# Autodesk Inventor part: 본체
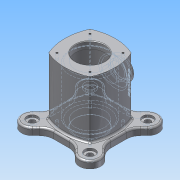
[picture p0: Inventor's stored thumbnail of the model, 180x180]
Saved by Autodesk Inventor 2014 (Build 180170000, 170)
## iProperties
Created: 2016-05
Part Number: 본체
Material: 알루미늄 6061
Document SubType Name: Modeling
Designer: Administrator
Density: 2.71 g/cm^3
Appearance: 알루미늄 - 평지
Mass: 1164.04 g
Surface Area: 856.901 cm^2
Volume: 429.534 cm^3
Author: Administrator
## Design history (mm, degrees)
sketch "스케치1"
  geometry: L1 (-43, 43)-(43, 43); L2 (43, 43)-(43, -43); L3 (43, -43)-(-43, -43); L4 (-43, -43)-(-43, 43); L5 (-43, 43)-(43, -43); L6 (43, 43)-(-43, -43); L7 (0, 0)-(35.355, 35.355); L8 (0, 0)-(-35.355, -35.355); L9 (0, 0)-(-35.355, 35.355); L10 (0, 0)-(35.355, -35.355); A1 r 85.579 centre (0, -42.579) between (35.355, 35.355) and (-35.355, 35.355); A2 r 86 centre (43, -0.091) between (-35.355, 35.355) and (-35.412, -35.412); A3 r 86 centre (-0.091, 43) between (-35.412, -35.412) and (35.355, -35.355); A4 r 85.579 centre (-42.579, 0) between (35.355, -35.355) and (35.355, 35.355)
  constraints: 20 end point, 9 point on circle, 5 point on line, 4 centre point, 4 tangent, 2 midpoint, 2 parallel, 1 horizontal, 1 perpendicular
  dimensions: "d1" = 86 distance of L2.end L3.end; "d2" = 86 distance of L1.end L2.end; "d3" = 50 distance of L7.start L7.end; "d4" = 50 distance of L7.start L8.end; "d5" = 50 distance of L7.start L9.end; "d6" = 50 distance of L7.start L10.end
extrude "돌출1" new body sketch "스케치1" distance "d7" = 110; taper "d8" = 0 deg
node "작업 평면1"
sketch "스케치2"
  geometry: L1 (35.355, 0)-(-35.355, 0) reference; C1 r 20 at (0, 61); 1 further point
  constraints: 1 centre point, 1 vertical alignment
  dimensions: "d10" = 40 diameter of C1; "d11" = 61 distance from line of L1 C1.centre
extrude "돌출2" join sketch "스케치2" stored distance "d12" = 110; taper "d13" = 10 deg
sketch "스케치4"
  geometry: C1 r 25 at (0, 0); 1 further point
  constraints: 1 centre point, 1 coincident
  dimensions: "d14" = 50 diameter of C1
extrude "돌출3" cut sketch "스케치4" stored distance "d15" = 110; taper "d16" = 0 deg
sketch "스케치5"
  geometry: L1 (0, 12)-(0, 98); L2 (-25, 110)-(25, 110) reference; L3 (55, 41)-(43, 38.884) reference; L4 (43, 38.884)-(43, 0) reference; L5 (43, 0)-(25, 0) reference; L6 (25, 0)-(25, 110) reference; L7 (25, 110)-(43, 110) reference; L8 (43, 110)-(43, 83.116) reference; L9 (43, 83.116)-(55, 81) reference; L10 (55, 81)-(55, 41) reference; L11 (-43, 0)-(-43, 110) reference; L12 (-43, 110)-(-25, 110) reference; L13 (-25, 110)-(-25, 0) reference; L14 (-25, 0)-(-43, 0) reference; L15 (0, 98)-(35, 98); L16 (35, 98)-(35, 12); L17 (35, 12)-(0, 12); 3 further points
  constraints: 9 end point, 2 midpoint, 2 perpendicular, 1 horizontal alignment, 1 parallel, 1 vertical alignment
  dimensions: "d20" = 86 distance of L1.start L1.end; "d21" = 35 distance of L15.end L1.end; "d22" = 86 distance of L15.end L16.end
revolve "회전1" sketch "스케치5" stored, may be unused: angle "d23" = 90 deg
hole "구멍1" diameter "d26" = 25; stored, may be unused: countersink angle "d30" = 90 deg, drill point angle "d32" = 118 deg; dims "d24" = 10, "d25" = 10, "d27" = 6, "d28" = 30, "d29" = 8, "d31" = 25
sketch "스케치9"
  geometry: L1 (-23.544, 49)-(23.544, 49); L2 (49, 23.544)-(49, -23.544); L3 (23.544, -49)-(-23.544, -49); L4 (-49, -23.544)-(-49, 23.544); L5 (-62.225, 36.77)-(-49, 23.544); L6 (-36.77, 62.225)-(-23.544, 49); L7 (49, -23.544)-(62.225, -36.77); L8 (23.544, -49)-(36.77, -62.225); L9 (36.77, 62.225)-(23.544, 49); L10 (49, 23.544)-(62.225, 36.77); L11 (-49, -23.544)-(-62.225, -36.77); L12 (-36.77, -62.225)-(-23.544, -49); C1 r 25 at (0, 0) reference; C2 r 25 at (0, 0); A1 r 85.579 centre (0, -42.579) between (35.355, 35.355) and (-35.355, 35.355) reference; A2 r 85.579 centre (42.579, 0) between (-35.355, 35.355) and (-35.355, -35.355) reference; A3 r 86 centre (0.091, 43) between (-35.355, -35.355) and (35.412, -35.412) reference; A4 r 86 centre (-43, -0.091) between (35.412, -35.412) and (35.355, 35.355) reference; A5 r 70 centre (0, 0) between (-35.239, 60.483) and (-60.483, -35.239); A6 r 18 centre (49.497, 49.497) between (62.225, 36.77) and (36.77, 62.225); A7 r 18 centre (-49.497, 49.497) between (-36.77, 62.225) and (-62.225, 36.77); A8 r 18 centre (-49.497, -49.497) between (-62.225, -36.77) and (-36.77, -62.225); A9 r 18 centre (49.497, -49.497) between (36.77, -62.225) and (62.225, -36.77)
  constraints: 24 end point, 10 point on circle, 6 centre point, 2 coincident, 2 parallel, 1 horizontal, 1 perpendicular
  dimensions: "d48" = 140 diameter of A5; "d49" = 36 diameter of A6; "d50" = 36 diameter of A7; "d51" = 36 diameter of A8; "d52" = 36 diameter of A9; "d59" = 98 distance between parallel lines of L2 L4; "d60" = 98 distance between parallel lines of L3 L1; "d61" = 36 distance between parallel lines of L6 L5; "d62" = 36 distance between parallel lines of L12 L11; "d63" = 36 distance between parallel lines of L7 L8; "d64" = 36 distance between parallel lines of L9 L10; "d65" = 50 diameter of C2; "d66" = 49 distance from line of L1 C2.centre; "d67" = 49 distance from line of L2 C1.centre; "d68" = 49.49747 horizontal distance of A6.centre C1.centre; "d69" = 90 deg angle of L11 L5; "d70" = 135 deg angle of L7 L2; "d71" = 90 deg angle of L7 L10; "d72" = 90 deg angle of L12 L8; "d73" = 49.49747 horizontal distance of A9.centre C1.centre; "d74" = 49.49747 horizontal distance of A8.centre C2.centre
extrude "돌출5" join sketch "스케치9" distance "d75" = 12; taper "d76" = 0 deg
fillet "모깎기1" dims "d77" = 25
sketch "스케치12"
  geometry: L1 (-49, -13.189)-(-49, 13.189) reference; L2 (-56.322, 30.866)-(-62.225, 36.77) reference; L3 (-36.77, 62.225)-(-30.866, 56.322) reference; L4 (-13.189, 49)-(13.189, 49) reference; L5 (30.866, 56.322)-(36.77, 62.225) reference; L6 (62.225, 36.77)-(56.322, 30.866) reference; L7 (49, 13.189)-(49, -13.189) reference; L8 (56.322, -30.866)-(62.225, -36.77) reference; L9 (36.77, -62.225)-(30.866, -56.322) reference; L10 (13.189, -49)-(-13.189, -49) reference; L11 (-30.866, -56.322)-(-36.77, -62.225) reference; L12 (-62.225, -36.77)-(-56.322, -30.866) reference; C1 r 25 at (0, 0) reference; A1 r 18 centre (49.497, -49.497) between (36.77, -62.225) and (62.225, -36.77) reference; A2 r 18 centre (49.497, 49.497) between (62.225, 36.77) and (36.77, 62.225) reference; A3 r 18 centre (-49.497, 49.497) between (-36.77, 62.225) and (-62.225, 36.77) reference; A4 r 25 centre (-74, -13.189) between (-56.322, -30.866) and (-49, -13.189) reference; A5 r 25 centre (-74, 13.189) between (-49, 13.189) and (-56.322, 30.866) reference; A6 r 18 centre (-49.497, 49.497) between (-36.77, 62.225) and (-62.225, 36.77) reference; A7 r 25 centre (-13.189, 74) between (-30.866, 56.322) and (-13.189, 49) reference; A8 r 25 centre (13.189, 74) between (13.189, 49) and (30.866, 56.322) reference; A9 r 18 centre (49.497, 49.497) between (62.225, 36.77) and (36.77, 62.225) reference; A10 r 25 centre (74, 13.189) between (56.322, 30.866) and (49, 13.189) reference; A11 r 25 centre (74, -13.189) between (49, -13.189) and (56.322, -30.866) reference; A12 r 18 centre (49.497, -49.497) between (36.77, -62.225) and (62.225, -36.77) reference; A13 r 25 centre (13.189, -74) between (30.866, -56.322) and (13.189, -49) reference; A14 r 25 centre (-13.189, -74) between (-13.189, -49) and (-30.866, -56.322) reference; A15 r 18 centre (-49.497, -49.497) between (-62.225, -36.77) and (-36.77, -62.225) reference
hole "구멍2" sketch "스케치12" at (49.497, 49.497), (-49.497, 49.497), (-49.497, -49.497), (49.497, -49.497) diameter "d78" = 10; stored, may be unused: countersink angle "d82" = 90 deg, drill point angle "d84" = 118 deg; dims "d79" = 6, "d80" = 4, "d81" = 2, "d83" = 8
sketch "스케치13"
  geometry: C1 r 5 at (49.497, -49.497) reference; C2 r 5 at (-49.497, 49.497) reference; C3 r 5 at (49.497, 49.497) reference; C4 r 5 at (-49.497, -49.497) reference; C5 r 9 at (-49.497, 49.497); C6 r 9 at (49.497, 49.497); C7 r 9 at (-49.497, -49.497); C8 r 9 at (49.497, -49.497); A1 r 18 centre (49.497, 49.497) between (62.225, 36.77) and (36.77, 62.225) reference; A2 r 18 centre (-49.497, 49.497) between (-36.77, 62.225) and (-62.225, 36.77) reference; A3 r 18 centre (-49.497, -49.497) between (-62.225, -36.77) and (-36.77, -62.225) reference; A4 r 18 centre (49.497, -49.497) between (36.77, -62.225) and (62.225, -36.77) reference; 1 further point
  constraints: 4 centre point, 4 coincident
  dimensions: "d85" = 18 diameter of C5; "d86" = 18 diameter of C6; "d87" = 18 diameter of C7; "d88" = 18 diameter of C8
extrude "돌출6" cut sketch "스케치13" distance "d89" = 4; taper "d90" = 0 deg
sketch "스케치14" dims "d91" = 80
  geometry: L1 (0, 0)-(28.284, 28.284); L2 (0, 0)-(45, 0); C1 r 25 at (0, 0) reference; 1 further point
  constraints: 4 end point, 2 coincident, 1 horizontal, 3 other
  dimensions: "d93" = 45 deg angle of L2 L1
hole "구멍3" sketch "스케치14" at (28.284, 28.284) diameter "d94" = 3.242; stored, may be unused: countersink angle "d98" = 90 deg, drill point angle "d100" = 118 deg; dims "d95" = 7, "d96" = 4, "d97" = 2, "d99" = 10
fillet "모깎기2" dims "d104" = 3
sketch "스케치15" dims "d105" = 80
  geometry: L1 (-62.225, 36.77)-(-56.322, 30.866) reference; L2 (0, 0)-(28.284, 28.284); L3 (0, 0)-(45, 0); C1 r 25 at (0, 0) reference; 1 further point
  constraints: 4 end point, 2 coincident, 1 horizontal, 1 perpendicular, 3 other
  dimensions: "d107" = 45 deg angle of L3 L2 (derived)
hole "구멍4" sketch "스케치15" at (28.284, 28.284) diameter "d108" = 3.242; stored, may be unused: countersink angle "d112" = 90 deg, drill point angle "d114" = 118 deg; dims "d109" = 7, "d110" = 4, "d111" = 2, "d113" = 10
fillet "모깎기3" dims "d118" = 3
fillet "모깎기4" dims "d119" = 3
fillet "모깎기5" dims "d120" = 3
fillet "모깎기6" dims "d121" = 3
chamfer "모따기1" distance "d122" = 1; stored, may be unused: second distance "d123" = 2, angle "d124" = 45 deg
chamfer "모따기2" distance "d125" = 1; stored, may be unused: second distance "d126" = 2, angle "d127" = 45 deg
chamfer "모따기3" distance "d128" = 1; stored, may be unused: second distance "d129" = 2, angle "d130" = 45 deg
node "작업 평면2"
sketch "스케치16"
  geometry: L1 (-35.833, 110)-(-43, 110) reference; L2 (-64.497, 12)-(-58.497, 12) reference; L3 (-58.497, 12)-(-58.497, 8) reference; L4 (-58.497, 8)-(-54.497, 8) reference; L5 (-54.497, 8)-(-54.497, 0) reference; L6 (-54.497, 0)-(-67.497, 0) reference; L7 (-67.497, 0)-(-67.497, 9) reference; L8 (-40.497, 12)-(-26.744, 12) reference; L9 (-18.164, 9)-(-18.164, 0) reference; L10 (-18.164, 0)-(-44.497, 0) reference; L11 (-44.497, 0)-(-44.497, 8) reference; L12 (-44.497, 8)-(-40.497, 8) reference; L13 (-40.497, 8)-(-40.497, 12) reference; L14 (26.744, 12)-(40.497, 12) reference; L15 (40.497, 12)-(40.497, 8) reference; L16 (40.497, 8)-(44.497, 8) reference; L17 (44.497, 8)-(44.497, 0) reference; L18 (44.497, 0)-(18.164, 0) reference; L19 (18.164, 0)-(18.164, 9) reference; L20 (58.497, 12)-(64.497, 12) reference; L21 (67.497, 9)-(67.497, 0) reference; L22 (67.497, 0)-(54.497, 0) reference; L23 (54.497, 0)-(54.497, 8) reference; L24 (54.497, 8)-(58.497, 8) reference; L25 (58.497, 8)-(58.497, 12) reference; C1 r 15 at (0, 61) reference; C2 r 20.97 at (0, 61) reference; 3 further points
  constraints: 5 other
  dimensions: "d132" = 49 distance from line of L1 point (-29, 61); "d133" = 29 distance of point (-29, 61) C1.centre
feature "엠보싱1" sketch "스케치16" dims "d1" = 86, "d2" = 86, "d3" = 50, "d4" = 50, "d5" = 50, "d6" = 50, "d134" = 0.5, "d135" = 0
node "솔리드1"
pattern_circular "원형 패턴1" dims angle "d102" = 360 deg
pattern_circular "원형 패턴2" dims angle "d116" = 360 deg
node "절단 모서리 투영1"
node "절단 모서리 투영2"
node "절단 모서리 투영3"
other parameters: "d9" = 55, "d55" = 18, "d56" = 18, "d57" = 18, "d58" = 18, "d131" = 49.5
